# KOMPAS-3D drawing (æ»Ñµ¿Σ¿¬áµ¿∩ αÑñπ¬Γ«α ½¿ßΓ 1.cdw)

Referenced files: 1.cdw
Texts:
  ПЛК.303120.01 СБ
  Редуктор  цилиндрический двухступенчатый
  Назаров Андрей
  Noncommercial version
  Сборочный чертеж
  Редуктор
  цилиндрический
  двухступенчатый
  Крышка подшипника сквозная
  Крышка подшипника глухая
  Вал тихоходный
  Колесо быстроходное
  Колесо тихоходное
  Крышка редуктора
  Корпус редуктора
  Сталь 45
  СЧ 15
  ПШП.РЧО.140.00.00 СП-
  Вал-шестерня быстроходный
  Вал-шестерня промежуточный
  ПЛК.305354.01 СБ
  Сборочные единицы
  Крышка-отдушина
  ПЛК.305456.01 СБ
  Маслоуказатель жезловый
  Детали
  Пробка сливная
  Сталь 3
  Втулка
  Втулка распорная
  Вавилин В.В
  Документация
Dimensions and other numbers on the sheet: 1:1; 3; 1; 5; 6; 7; 8; 9; 10; 11; 12; 13; 14; 2; 4; 15; 16; 17; 18; 0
